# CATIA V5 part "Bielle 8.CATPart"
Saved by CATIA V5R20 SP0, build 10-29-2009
Part number: Bielle 8
Bounding box of the stored display mesh (mm): x -30 to 70, y 99.486 to 418.624, z -169.811 to -34.432
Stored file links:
  D:\Dropbox\IAO_2011\MMS_GR1\0\video\IAO_2011_1503_rjugie\rjugie\IAO_2011_1503_rjugie\Bielle 8.CATPart
  D:\Dropbox\IAO_2011\MMS_GR1\0\video\IAO_2011_1503_rjugie\rjugie\IAO_2011_1503_rjugie\rjugie.CATProduct
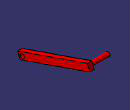
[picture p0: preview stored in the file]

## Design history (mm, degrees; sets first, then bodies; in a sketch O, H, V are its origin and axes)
External parameters (linked from other documents)
  External.Hauteur_bielle = 15 mm
  External.Rayon_trou_bielle = 10 mm
  External.Epaisseur_bielle = 20 mm
Set1
  Plane1: linked copy from another document
  Line1: linked copy from another document
  Point1 "E": linked copy from another document
  Point2 "C": linked copy from another document
Body1 (main body)
  Sketch1 on Plane1, origin (0, 0, 0), H (0, 1, 0), V (0, 0, 1)
    circle A1 centre (118.5657, -150.7309) radius 10
    point P1 (118.5657, -150.7309)
    reference projected point E1 (118.5657, -150.7309) from Point2
    line L1 (99.4855, -141.4601) -> (408.8143, -34.4321)
    point P3 (408.8143, -34.4321)
    line L2 (408.8143, -34.4321) -> (418.6237, -62.783)
    point P4 (408.8143, -34.4321)
    line L3 (418.6237, -62.783) -> (109.295, -169.811)
    reference projected line E2 (145.1752, -141.5239) -> (399.6325, -53.4814) from Line1
    line L4 (99.4855, -141.4601) -> (109.295, -169.811)
    reference projected line E3 (145.1752, -141.5239) -> (399.6325, -53.4814) from Line1
    reference projected line E4 (145.1752, -141.5239) -> (399.6325, -53.4814) from Line1
    reference projected line E5 (145.1752, -141.5239) -> (399.6325, -53.4814) from Line1
    reference projected line E6 (145.1752, -141.5239) -> (399.6325, -53.4814) from Line1
    reference projected line E7 (145.1752, -141.5239) -> (399.6325, -53.4814) from Line1
    reference projected point E8 (118.5657, -150.7309) from Point2
    reference projected point E9 (399.5435, -53.5122) from Point1
    radius A1 = 10 {= External.Rayon_trou_bielle}
    distance L1 E6 = 15 {= External.Hauteur_bielle}
    distance L3 E7 = 15 {= External.Hauteur_bielle}
    distance E8 L4 = 15 {= External.Hauteur_bielle}
    distance L2 E9 = 15 {= External.Hauteur_bielle}
    coincidence: P1 E1, P4 L1, P3 P4
    parallelism: L1 E2, L3 E3
    perpendicularity: L4 E4, L2 E5
  Pad1: profile Sketch1, direction (1, 0, 0), length 70 {= 50mm+External.Epaisseur_bielle}, opposite side length -50
  Sketch2 on Plane1, origin (0, 0, 0), H (0, 1, 0), V (0, 0, 1)
    circle A1 centre (399.5435, -53.5122) radius 10
    point P1 (399.5435, -53.5122)
    reference projected point E1 (399.5435, -53.5122) from Point1
    radius A1 = 10 {= External.Rayon_trou_bielle}
    coincidence: P1 E1
  Pad2: profile Sketch2, direction (1, 0, 0), length 50, opposite side length 30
